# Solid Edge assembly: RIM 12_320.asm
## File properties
Title: Zylinder
Author: ahadarics
Template: iso metric assembly.asm
Last saved by: ahadarics
Revision: 29
Application: Solid Edge
Username: ahadarics
Dokumentum tartalom típus: 1
Document Number: RIM 12/320
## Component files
Profilrohr.par
Kolbenstange.par
Kit_1.par
Kit_2.par
Mutter_1.par
Mutter_2.par
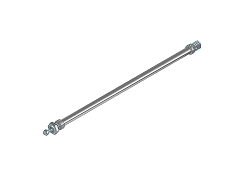
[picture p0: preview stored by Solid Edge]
